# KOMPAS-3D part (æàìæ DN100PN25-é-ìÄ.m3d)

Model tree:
1. Объединить компоненты:1  (labels: СЕНС DN100PN25-В-НО)

Referenced files in D:\Савин\!СЕНСОР\3D для заказчика\!Новый перечень\СЕНС\6. СЕНС-В-НО\DN100\: СЕНС DN100PN25-В-НО.a3d
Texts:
  СЕНС DN100PN25-В-НО
  ООО НПП Сенсор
